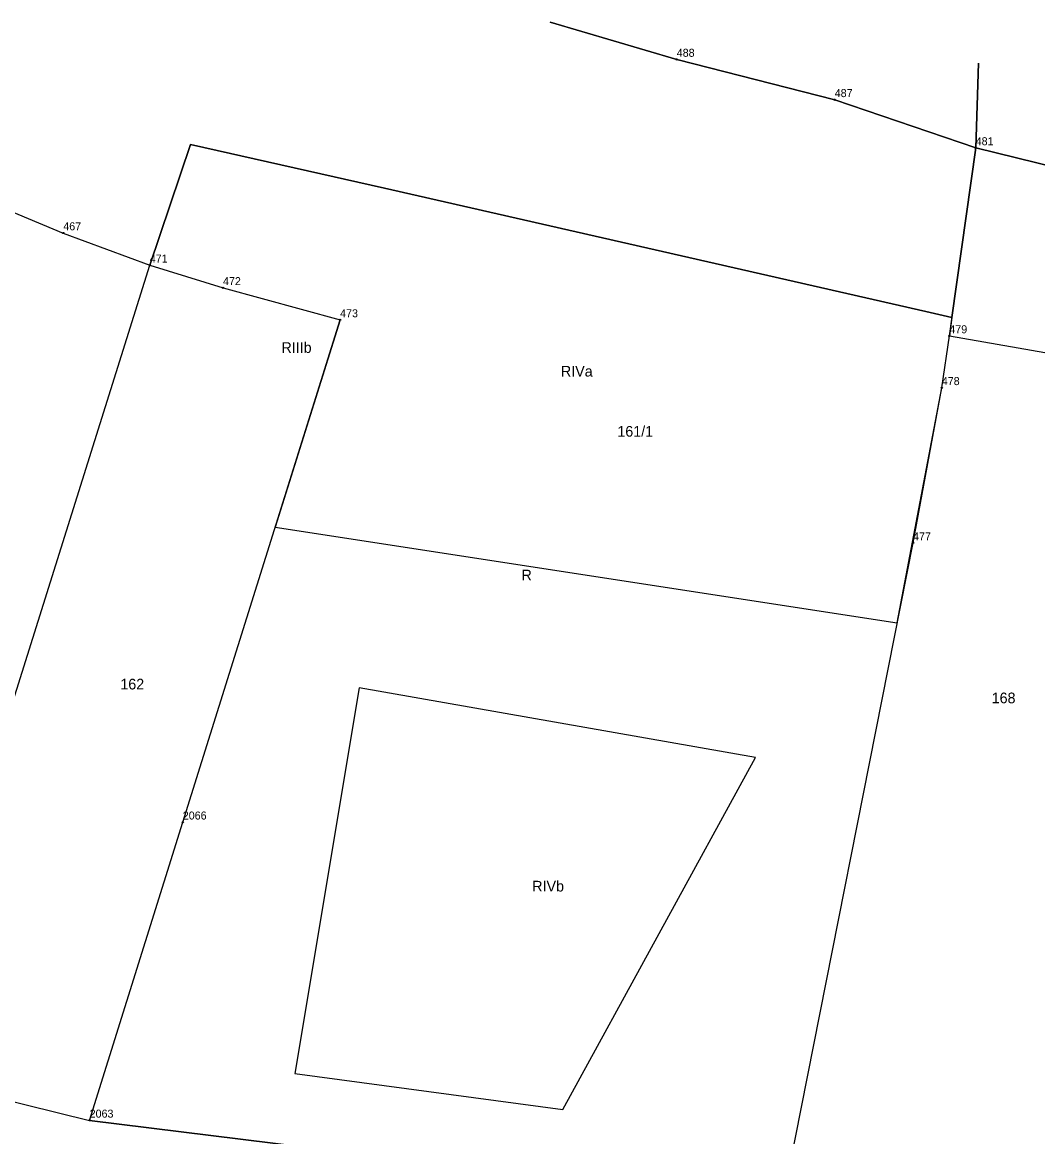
# Model space of a CAD drawing. Extents: x 7467189 to 7469366, y 5491487 to 5492734.
# Drawn here: x 7468171.1 to 7468314, y 5491705.1 to 5491861.8 of the extents above; entities that cross this region are included whole.
import ezdxf

# ---------------------------------------------------------------- set-up
doc = ezdxf.new("R2010")
doc.units = 0
for name, color, linetype in [('203-punkt graniczny', 7, 'Continuous'), ('203-punkt graniczny-Atr103', 7, 'Continuous'), ('209-oznaczenie konturu klasyfikacyjnego', 7, 'Continuous'), ('210-oznaczenie konturu użytku gruntowego', 7, 'Continuous'), ('211-numer działki ewidencyjnej', 7, 'Continuous'), ('217-kontur klasyfikacyjny', 7, 'Continuous'), ('218-kontur użytku gruntowego', 7, 'Continuous'), ('219-działka ewidencyjna', 7, 'Continuous')]:
    doc.layers.add(name, color=color, linetype=linetype)

# ---------------------------------------------------------------- blocks, each defined once
blk = doc.blocks.new('203')
blk.add_circle((0, 0), 0.09)

msp = doc.modelspace()

# ---------------------------------------------------------------- linework, layer by layer
at = {"layer": '217-kontur klasyfikacyjny'}
for points in [[(7468263.2, 5491856.55), (7468245.38, 5491861.77)], [(7468285.42, 5491850.88), (7468263.2, 5491856.55)], [(7468305.64, 5491856), (7468305.25, 5491844.1)], [(7468305.25, 5491844.1), (7468285.42, 5491850.88)], [(7468194.81, 5491844.57), (7468189.08, 5491827.61)], [(7468222.09, 5491838.46), (7468194.81, 5491844.57)], [(7468305.25, 5491844.1), (7468301.91, 5491820.28)], [(7468325.31, 5491839.21), (7468305.25, 5491844.1)], [(7468298.23, 5491821.12), (7468222.09, 5491838.46)], [(7468164.1, 5491837.47), (7468176.91, 5491832.14)], [(7468176.91, 5491832.14), (7468189.08, 5491827.61)], [(7468189.08, 5491827.61), (7468199.38, 5491824.43)], [(7468199.38, 5491824.43), (7468215.85, 5491819.91)], [(7468301.91, 5491820.28), (7468298.23, 5491821.12)], [(7468215.85, 5491819.91), (7468206.72, 5491790.76)], [(7468301.91, 5491820.28), (7468301.54, 5491817.66)], [(7468300.48, 5491810.38), (7468301.54, 5491817.66)], [(7468301.54, 5491817.66), (7468329.45, 5491812.82)], [(7468294.19, 5491777.32), (7468300.48, 5491810.38)], [(7468206.72, 5491790.76), (7468294.19, 5491777.32)], [(7468218.53, 5491768.18), (7468209.5, 5491713.95)], [(7468274.26, 5491758.38), (7468218.53, 5491768.18)], [(7468247.16, 5491708.9), (7468274.26, 5491758.38)], [(7468153.66, 5491713.99), (7468180.62, 5491707.36)], [(7468209.5, 5491713.95), (7468247.16, 5491708.9)], [(7468180.62, 5491707.36), (7468210.56, 5491703.64)]]:
    msp.add_lwpolyline(points, dxfattribs=at)
at = {"layer": '218-kontur użytku gruntowego'}
for points in [[(7468263.2, 5491856.55), (7468245.38, 5491861.77)], [(7468285.42, 5491850.88), (7468263.2, 5491856.55)], [(7468305.64, 5491856), (7468305.25, 5491844.1)], [(7468305.25, 5491844.1), (7468285.42, 5491850.88)], [(7468189.08, 5491827.61), (7468194.81, 5491844.57)], [(7468194.81, 5491844.57), (7468222.09, 5491838.46)], [(7468301.91, 5491820.28), (7468305.25, 5491844.1)], [(7468305.25, 5491844.1), (7468325.31, 5491839.21)], [(7468222.09, 5491838.46), (7468298.23, 5491821.12)], [(7468164.1, 5491837.47), (7468176.91, 5491832.14)], [(7468176.91, 5491832.14), (7468189.08, 5491827.61)], [(7468298.23, 5491821.12), (7468301.91, 5491820.28)], [(7468153.66, 5491713.99), (7468180.62, 5491707.36)], [(7468180.62, 5491707.36), (7468210.56, 5491703.64)]]:
    msp.add_lwpolyline(points, dxfattribs=at)
at = {"layer": '219-działka ewidencyjna'}
for points in [[(7468245.38, 5491861.77), (7468263.2, 5491856.55)], [(7468263.2, 5491856.55), (7468285.42, 5491850.88)], [(7468305.25, 5491844.1), (7468305.64, 5491856)], [(7468285.42, 5491850.88), (7468305.25, 5491844.1)], [(7468301.54, 5491817.66), (7468305.25, 5491844.1)], [(7468305.25, 5491844.1), (7468325.31, 5491839.21)], [(7468164.1, 5491837.47), (7468176.91, 5491832.14)], [(7468176.91, 5491832.14), (7468189.08, 5491827.61)], [(7468166.34, 5491755.29), (7468189.08, 5491827.61)], [(7468189.08, 5491827.61), (7468199.38, 5491824.43)], [(7468199.38, 5491824.43), (7468215.85, 5491819.91)], [(7468193.72, 5491749.28), (7468215.85, 5491819.91)], [(7468300.48, 5491810.38), (7468301.54, 5491817.66)], [(7468296.44, 5491788.55), (7468300.48, 5491810.38)], [(7468278.14, 5491695.95), (7468296.44, 5491788.55)], [(7468180.62, 5491707.36), (7468193.72, 5491749.28)], [(7468153.66, 5491713.99), (7468180.62, 5491707.36)], [(7468210.56, 5491703.64), (7468180.62, 5491707.36)]]:
    msp.add_lwpolyline(points, dxfattribs=at)

# ---------------------------------------------------------------- block references
at = {"layer": '203-punkt graniczny'}
for p in [(7468263.2, 5491856.55), (7468285.42, 5491850.88), (7468305.25, 5491844.1), (7468176.91, 5491832.14), (7468189.08, 5491827.61), (7468199.38, 5491824.43), (7468215.85, 5491819.91), (7468301.54, 5491817.66), (7468300.48, 5491810.38), (7468296.44, 5491788.55), (7468193.72, 5491749.28), (7468180.62, 5491707.36)]:
    msp.add_blockref('203', p, dxfattribs=at)

# ---------------------------------------------------------------- texts
at = {"layer": '203-punkt graniczny-Atr103'}
for s, p in [('488', (7468263.2, 5491856.92)), ('487', (7468285.42, 5491851.25)), ('481', (7468305.25, 5491844.48)), ('467', (7468176.91, 5491832.52)), ('471', (7468189.08, 5491827.99)), ('472', (7468199.38, 5491824.81)), ('473', (7468215.85, 5491820.29)), ('479', (7468301.54, 5491818.04)), ('478', (7468300.48, 5491810.75)), ('477', (7468296.44, 5491788.92)), ('2066', (7468193.72, 5491749.66)), ('2063', (7468180.62, 5491707.74))]:
    msp.add_text(s, height=1.125, dxfattribs=at).set_placement(p)
at = {"layer": '209-oznaczenie konturu klasyfikacyjnego'}
for s, p in [('RIIIb', (7468207.6, 5491815.28)), ('RIVa', (7468246.91, 5491811.95)), ('RIVb', (7468242.88, 5491739.54))]:
    msp.add_text(s, height=1.5, dxfattribs=at).set_placement(p)
at = {"layer": '210-oznaczenie konturu użytku gruntowego'}
msp.add_text('R', height=1.5, dxfattribs=at).set_placement((7468241.37, 5491783.29))
at = {"layer": '211-numer działki ewidencyjnej'}
for s, p in [('161/1', (7468254.85, 5491803.5)), ('162', (7468184.94, 5491767.95)), ('168', (7468307.5, 5491766.01))]:
    msp.add_text(s, height=1.5, dxfattribs=at).set_placement(p)

doc.saveas('drawing.dxf')
